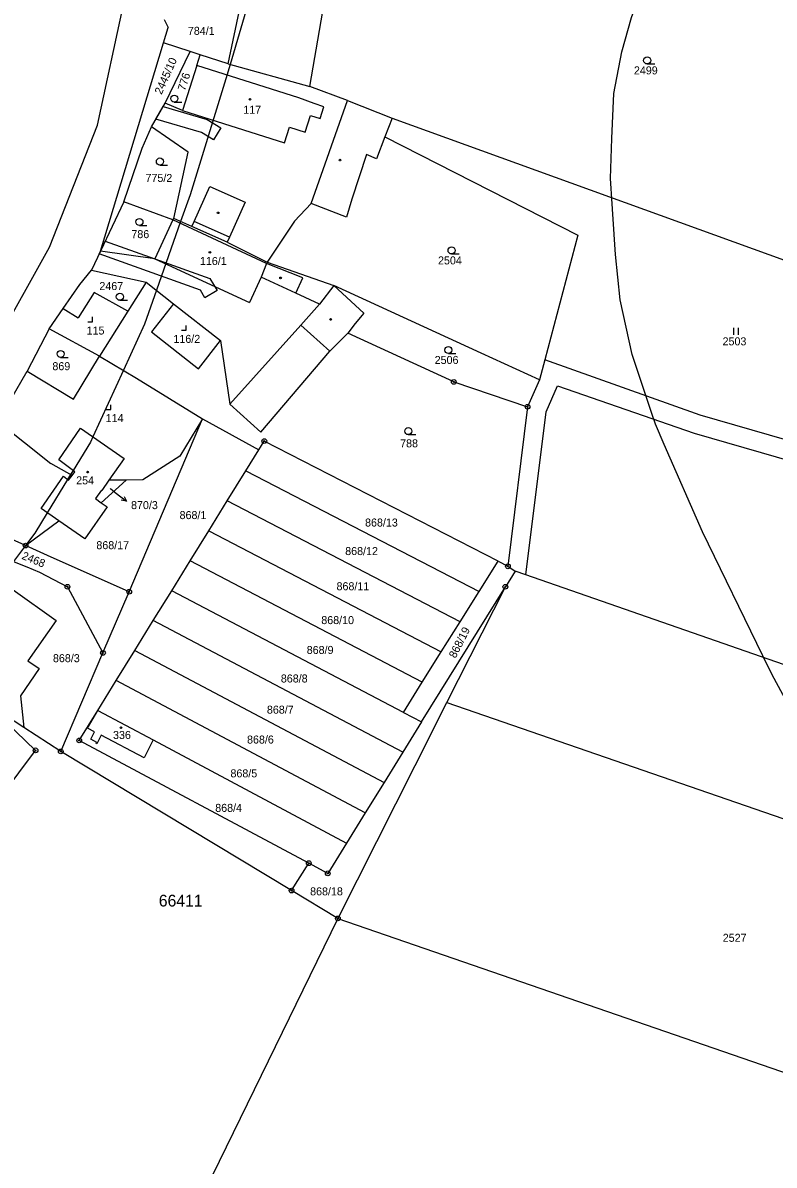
# Model space of a CAD drawing. Extents: x -546762 to -540209, y -1046851 to -1035694.
# Drawn here: x -542624.6 to -542465, y -1040034.9 to -1039792.3 of the extents above; entities that cross this region are included whole.
import ezdxf

# ---------------------------------------------------------------- set-up
doc = ezdxf.new("R2010")
doc.units = 0
for name, color, linetype in [('Vrstva 1', 7, 'Continuous'), ('Vrstva 16', 7, 'Continuous'), ('Vrstva 18', 7, 'Continuous'), ('Vrstva 19', 7, 'Continuous'), ('Vrstva 24', 7, 'Continuous'), ('Vrstva 25', 7, 'Continuous'), ('Vrstva 3', 7, 'Continuous'), ('Vrstva 30', 7, 'Continuous'), ('Vrstva 37', 7, 'Continuous'), ('Vrstva 4', 7, 'Continuous'), ('Vrstva 52', 7, 'Continuous'), ('Vrstva 53', 7, 'Continuous')]:
    doc.layers.add(name, color=color, linetype=linetype)

msp = doc.modelspace()

# ---------------------------------------------------------------- linework, layer by layer
at = {"layer": 'Vrstva 1'}
for p, q in [((-542581, -1039801.03), (-542563.71, -1039805.78)), ((-542581.25, -1039838.88), (-542572.71, -1039843.1)), ((-542559.45, -1039862.04), (-542555.64, -1039858.16)), ((-542523.68, -1039906.64), (-542573.35, -1039881.1)), ((-542577.28, -1039887.46), (-542527.73, -1039913.09)), ((-542531.75, -1039919.5), (-542581.21, -1039893.81)), ((-542585.14, -1039900.17), (-542535.77, -1039925.9)), ((-542539.79, -1039932.31), (-542589.07, -1039906.53)), ((-542527.73, -1039913.09), (-542523.68, -1039906.64)), ((-542523.68, -1039906.64), (-542521.61, -1039907.71)), ((-542543.81, -1039938.73), (-542593.01, -1039912.89)), ((-542531.75, -1039919.5), (-542527.73, -1039913.09)), ((-542535.77, -1039925.9), (-542531.75, -1039919.5)), ((-542539.79, -1039932.31), (-542535.77, -1039925.9)), ((-542543.81, -1039938.73), (-542539.79, -1039932.31)), ((-542625.15, -1039935.18), (-542624.41, -1039941.95)), ((-542610.93, -1039942.11), (-542608.73, -1039938.31)), ((-542608.73, -1039938.31), (-542596.99, -1039944.57)), ((-542543.81, -1039938.73), (-542539.94, -1039940.76)), ((-542609.4, -1039942.89), (-542610.93, -1039942.11)), ((-542610.19, -1039944.45), (-542609.4, -1039942.89)), ((-542608.94, -1039945.09), (-542610.19, -1039944.45)), ((-542608.02, -1039943.6), (-542608.91, -1039945.42)), ((-542598.87, -1039948.36), (-542608.02, -1039943.6)), ((-542596.99, -1039944.57), (-542598.87, -1039948.36)), ((-542596.99, -1039944.57), (-542555.88, -1039966.48)), ((-542563.91, -1039970.75), (-542612.66, -1039944.67)), ((-542609.06, -1039945.33), (-542608.94, -1039945.09)), ((-542608.91, -1039945.42), (-542609.06, -1039945.33)), ((-542567.56, -1039976.57), (-542563.91, -1039970.75)), ((-542559.87, -1039972.91), (-542563.91, -1039970.75))]:
    msp.add_line(p, q, dxfattribs=at)
for points in [[(-542563.71, -1039805.78), (-542556.45, -1039763.93)], [(-542581, -1039801.03), (-542575.76, -1039776.13)], [(-542608.77, -1039813.99), (-542603.21, -1039788.14)], [(-542594.65, -1039791.59), (-542593.79, -1039793.26)], [(-542594.79, -1039796.56), (-542593.79, -1039793.26)], [(-542608.16, -1039840.77), (-542594.79, -1039796.56)], [(-542589.11, -1039798.4), (-542594.79, -1039796.56)], [(-542594.42, -1039809.35), (-542589.11, -1039798.4)], [(-542586.96, -1039799.1), (-542589.11, -1039798.4)], [(-542587.67, -1039801.32), (-542590.72, -1039810.88)], [(-542587.67, -1039801.32), (-542586.96, -1039799.1)], [(-542581, -1039801.03), (-542586.96, -1039799.1)], [(-542555.67, -1039808.79), (-542563.71, -1039805.78)], [(-542555.67, -1039808.79), (-542546.21, -1039812.5)], [(-542597.33, -1039814.38), (-542594.42, -1039809.35)], [(-542590.72, -1039810.88), (-542594.42, -1039809.35)], [(-542546.21, -1039812.5), (-542547.73, -1039816.49)], [(-542546.21, -1039812.5), (-542443.07, -1039849.82)], [(-542619, -1039839.94), (-542608.77, -1039813.99)], [(-542599.3, -1039818.9), (-542597.33, -1039814.38)], [(-542589.53, -1039819.73), (-542597.33, -1039814.38)], [(-542547.73, -1039816.49), (-542549.53, -1039821.2)], [(-542547.73, -1039816.49), (-542506.75, -1039837.36)], [(-542603.17, -1039830.3), (-542599.3, -1039818.9)], [(-542592.6, -1039833.81), (-542589.53, -1039819.73)], [(-542551.62, -1039820.28), (-542554.73, -1039829.75)], [(-542549.53, -1039821.2), (-542551.62, -1039820.28)], [(-542603.17, -1039830.3), (-542608.16, -1039840.77)], [(-542592.75, -1039834.13), (-542603.17, -1039830.3)], [(-542563.38, -1039830.63), (-542566.95, -1039834.4)], [(-542555.92, -1039833.53), (-542563.38, -1039830.63)], [(-542554.73, -1039829.75), (-542555.92, -1039833.53)], [(-542592.75, -1039834.13), (-542596.61, -1039842.42)], [(-542592.75, -1039834.13), (-542592.6, -1039833.81)], [(-542588.72, -1039835.54), (-542592.6, -1039833.81)], [(-542566.95, -1039834.4), (-542572.71, -1039843.1)], [(-542581.25, -1039838.88), (-542588.72, -1039835.54)], [(-542506.75, -1039837.36), (-542513.76, -1039863.86)], [(-542630.3, -1039860.17), (-542619, -1039839.94)], [(-542608.16, -1039840.77), (-542610.07, -1039844.79)], [(-542596.61, -1039842.42), (-542608.16, -1039840.77)], [(-542612.57, -1039847.88), (-542610.07, -1039844.79)], [(-542610.07, -1039844.79), (-542598.45, -1039847.35)], [(-542572.71, -1039843.1), (-542558.58, -1039848.09)], [(-542598.45, -1039847.35), (-542602.33, -1039853.54)], [(-542598.45, -1039847.35), (-542592.62, -1039851.93)], [(-542616.08, -1039852.98), (-542612.57, -1039847.88)], [(-542609.51, -1039849.57), (-542612.9, -1039854.97)], [(-542602.33, -1039853.54), (-542609.51, -1039849.57)], [(-542527.27, -1039862.42), (-542558.58, -1039848.09)], [(-542558.58, -1039848.09), (-542552.22, -1039853.95)], [(-542592.62, -1039851.93), (-542597.31, -1039857.91)], [(-542592.62, -1039851.93), (-542582.67, -1039859.75)], [(-542619.07, -1039857.3), (-542616.08, -1039852.98)], [(-542616.08, -1039852.98), (-542612.9, -1039854.97)], [(-542602.33, -1039853.54), (-542608.33, -1039863.11)], [(-542552.22, -1039853.95), (-542554.03, -1039856.17)], [(-542619.07, -1039857.3), (-542623.71, -1039866.26)], [(-542608.33, -1039863.11), (-542619.07, -1039857.3)], [(-542554.03, -1039856.17), (-542555.64, -1039858.16)], [(-542597.31, -1039857.91), (-542587.33, -1039865.76)], [(-542533.1, -1039868.56), (-542555.64, -1039858.16)], [(-542587.33, -1039865.76), (-542582.67, -1039859.75)], [(-542582.67, -1039859.75), (-542580.71, -1039873.25)], [(-542574.09, -1039879.21), (-542559.45, -1039862.04)], [(-542613.91, -1039872.24), (-542608.33, -1039863.11)], [(-542608.33, -1039863.11), (-542600.49, -1039867.72)], [(-542514.88, -1039868.09), (-542527.27, -1039862.42)], [(-542513.76, -1039863.86), (-542514.88, -1039868.09)], [(-542480.8, -1039875.6), (-542513.76, -1039863.86)], [(-542629.96, -1039876.96), (-542623.71, -1039866.26)], [(-542623.71, -1039866.26), (-542613.91, -1039872.24)], [(-542600.49, -1039867.72), (-542586.46, -1039876.4)], [(-542533.1, -1039868.56), (-542517.43, -1039873.82)], [(-542514.88, -1039868.09), (-542517.43, -1039873.82)], [(-542513.5, -1039874.91), (-542511.05, -1039869.41)], [(-542511.05, -1039869.41), (-542482.01, -1039879.41)], [(-542580.71, -1039873.25), (-542574.09, -1039879.21)], [(-542517.43, -1039873.82), (-542521.61, -1039907.71)], [(-542602.05, -1039913.1), (-542586.46, -1039876.4)], [(-542586.46, -1039876.4), (-542591.3, -1039884.34)], [(-542586.46, -1039876.4), (-542574.5, -1039882.96)], [(-542517.77, -1039909.55), (-542513.5, -1039874.91)], [(-542425.03, -1039891.71), (-542480.8, -1039875.6)], [(-542629.96, -1039876.96), (-542618.71, -1039885.88)], [(-542617.03, -1039885.08), (-542612.4, -1039878.35)], [(-542612.4, -1039878.35), (-542603.11, -1039884.79)], [(-542574.5, -1039882.96), (-542573.35, -1039881.1)], [(-542482.01, -1039879.41), (-542443.54, -1039890.54)], [(-542577.28, -1039887.46), (-542574.5, -1039882.96)], [(-542614.19, -1039888.41), (-542618.71, -1039885.88)], [(-542613.6, -1039887.61), (-542617.03, -1039885.08)], [(-542603.11, -1039884.79), (-542606.36, -1039889.43)], [(-542591.3, -1039884.34), (-542599.17, -1039889.37)], [(-542620.78, -1039895.41), (-542616.04, -1039888.58)], [(-542616.04, -1039888.58), (-542614.92, -1039889.4)], [(-542614.92, -1039889.4), (-542614.19, -1039888.41)], [(-542614.19, -1039888.41), (-542613.6, -1039887.61)], [(-542581.21, -1039893.81), (-542577.28, -1039887.46)], [(-542602.68, -1039889.4), (-542607.98, -1039894.2)], [(-542606.36, -1039889.43), (-542607.87, -1039891.59)], [(-542602.68, -1039889.4), (-542606.36, -1039889.43)], [(-542599.17, -1039889.37), (-542602.68, -1039889.4)], [(-542607.95, -1039891.53), (-542609.21, -1039893.34)], [(-542609.21, -1039893.34), (-542607.98, -1039894.2)], [(-542607.87, -1039891.59), (-542607.95, -1039891.53)], [(-542617.01, -1039898.03), (-542620.78, -1039895.41)], [(-542606.75, -1039895.06), (-542611.51, -1039901.86)], [(-542607.98, -1039894.2), (-542606.75, -1039895.06)], [(-542585.14, -1039900.17), (-542581.21, -1039893.81)], [(-542624.06, -1039903.31), (-542617.01, -1039898.03)], [(-542611.51, -1039901.86), (-542617.01, -1039898.03)], [(-542624.06, -1039903.31), (-542633.71, -1039898.96)], [(-542589.07, -1039906.53), (-542585.14, -1039900.17)], [(-542619.41, -1039905.38), (-542624.06, -1039903.31)], [(-542602.05, -1039913.1), (-542619.41, -1039905.38)], [(-542627.89, -1039906.22), (-542623.78, -1039907.79)], [(-542623.78, -1039907.79), (-542621.09, -1039908.93)], [(-542593.01, -1039912.89), (-542589.07, -1039906.53)], [(-542521.61, -1039907.71), (-542520.07, -1039908.75)], [(-542621.09, -1039908.93), (-542615.16, -1039912.05)], [(-542520.07, -1039908.75), (-542522.15, -1039912.06)], [(-542517.77, -1039909.55), (-542520.07, -1039908.75)], [(-542408.09, -1039947.65), (-542517.77, -1039909.55)], [(-542626.73, -1039912.72), (-542617.54, -1039919.22)], [(-542615.16, -1039912.05), (-542607.62, -1039926.1)], [(-542607.62, -1039926.1), (-542602.05, -1039913.1)], [(-542596.94, -1039919.24), (-542593.01, -1039912.89)], [(-542539.94, -1039940.76), (-542522.15, -1039912.06)], [(-542534.56, -1039936.63), (-542522.15, -1039912.06)], [(-542617.54, -1039919.22), (-542623.6, -1039927.8)], [(-542600.87, -1039925.6), (-542596.94, -1039919.24)], [(-542543.92, -1039947.19), (-542596.94, -1039919.24)], [(-542616.59, -1039947.02), (-542607.62, -1039926.1)], [(-542604.8, -1039931.96), (-542600.87, -1039925.6)], [(-542600.87, -1039925.6), (-542547.91, -1039953.62)], [(-542621.15, -1039929.4), (-542625.15, -1039935.18)], [(-542623.6, -1039927.8), (-542621.15, -1039929.4)], [(-542608.73, -1039938.31), (-542604.8, -1039931.96)], [(-542551.9, -1039960.05), (-542604.8, -1039931.96)], [(-542624.41, -1039941.95), (-542632.54, -1039936.68)], [(-542632.54, -1039936.68), (-542621.94, -1039946.79)], [(-542537.24, -1039941.94), (-542534.56, -1039936.63)], [(-542534.56, -1039936.63), (-542397.78, -1039983.83)], [(-542612.66, -1039944.67), (-542608.73, -1039938.31)], [(-542616.59, -1039947.02), (-542624.41, -1039941.95)], [(-542537.24, -1039941.94), (-542557.72, -1039982.5)], [(-542539.94, -1039940.76), (-542543.92, -1039947.19)], [(-542667.2, -1040007.38), (-542621.94, -1039946.79)], [(-542567.56, -1039976.57), (-542616.59, -1039947.02)], [(-542543.92, -1039947.19), (-542547.91, -1039953.62)], [(-542547.91, -1039953.62), (-542551.9, -1039960.05)], [(-542551.9, -1039960.05), (-542555.88, -1039966.48)], [(-542555.88, -1039966.48), (-542559.87, -1039972.91)], [(-542557.72, -1039982.5), (-542567.56, -1039976.57)], [(-542557.72, -1039982.5), (-542615.49, -1040100.81)], [(-542557.72, -1039982.5), (-542416.72, -1040031.16)]]:
    msp.add_lwpolyline(points, dxfattribs=at)
at = {"layer": 'Vrstva 16'}
msp.add_line((-542605.02, -1039892.01), (-542602.66, -1039893.86), dxfattribs=at)
for points in [[(-542606.03, -1039891.21), (-542605.02, -1039892.01)], [(-542603.14, -1039892.85), (-542602.66, -1039893.86), (-542603.76, -1039893.64)]]:
    msp.add_lwpolyline(points, dxfattribs=at)
at = {"layer": 'Vrstva 24'}
for centre, radius in [((-542533.1, -1039868.56), 0.5), ((-542533.1, -1039868.56), 0.1), ((-542517.43, -1039873.82), 0.5), ((-542517.43, -1039873.82), 0.1), ((-542573.35, -1039881.1), 0.5), ((-542573.35, -1039881.1), 0.1), ((-542624.06, -1039903.31), 0.5), ((-542624.06, -1039903.31), 0.1), ((-542521.61, -1039907.71), 0.5), ((-542521.61, -1039907.71), 0.1), ((-542615.16, -1039912.05), 0.5), ((-542615.16, -1039912.05), 0.1), ((-542602.05, -1039913.1), 0.5), ((-542602.05, -1039913.1), 0.1), ((-542522.15, -1039912.06), 0.5), ((-542522.15, -1039912.06), 0.1), ((-542607.62, -1039926.1), 0.5), ((-542607.62, -1039926.1), 0.1), ((-542612.66, -1039944.67), 0.5), ((-542612.66, -1039944.67), 0.1), ((-542621.94, -1039946.79), 0.5), ((-542621.94, -1039946.79), 0.1), ((-542616.59, -1039947.02), 0.5), ((-542616.59, -1039947.02), 0.1), ((-542563.91, -1039970.75), 0.5), ((-542563.91, -1039970.75), 0.1), ((-542559.87, -1039972.91), 0.5), ((-542559.87, -1039972.91), 0.1), ((-542567.56, -1039976.57), 0.5), ((-542567.56, -1039976.57), 0.1), ((-542557.72, -1039982.5), 0.5), ((-542557.72, -1039982.5), 0.1)]:
    msp.add_circle(centre, radius, dxfattribs=at)
at = {"layer": 'Vrstva 25'}
for p, q in [((-542492.02, -1039801.03), (-542490.42, -1039801.03)), ((-542592.48, -1039809.13), (-542590.88, -1039809.13)), ((-542595.53, -1039822.49), (-542593.93, -1039822.49)), ((-542599.88, -1039835.32), (-542598.28, -1039835.32)), ((-542533.58, -1039841.38), (-542531.98, -1039841.38)), ((-542604.04, -1039851.21), (-542602.44, -1039851.21)), ((-542473.63, -1039858.57), (-542473.63, -1039857.07)), ((-542472.63, -1039858.57), (-542472.63, -1039857.07)), ((-542616.62, -1039863.36), (-542615.02, -1039863.36)), ((-542534.25, -1039862.52), (-542532.65, -1039862.52)), ((-542542.77, -1039879.74), (-542541.17, -1039879.74))]:
    msp.add_line(p, q, dxfattribs=at)
for points in [[(-542610.84, -1039855.76), (-542609.84, -1039855.76), (-542609.84, -1039854.76)], [(-542590.96, -1039857.57), (-542589.96, -1039857.57), (-542589.96, -1039856.57)], [(-542606.94, -1039874.38), (-542605.94, -1039874.38), (-542605.94, -1039873.38)]]:
    msp.add_lwpolyline(points, dxfattribs=at)
for centre, radius in [((-542492.02, -1039800.28), 0.75), ((-542592.48, -1039808.38), 0.75), ((-542576.38, -1039808.52), 0.175), ((-542595.53, -1039821.74), 0.75), ((-542557.29, -1039821.45), 0.175), ((-542583.16, -1039832.64), 0.175), ((-542599.88, -1039834.57), 0.75), ((-542533.58, -1039840.63), 0.75), ((-542584.92, -1039841.02), 0.175), ((-542569.91, -1039846.46), 0.175), ((-542604.04, -1039850.46), 0.75), ((-542559.26, -1039855.29), 0.175), ((-542616.62, -1039862.61), 0.75), ((-542534.25, -1039861.77), 0.75), ((-542542.77, -1039878.99), 0.75), ((-542610.88, -1039887.7), 0.175), ((-542603.8, -1039941.99), 0.175)]:
    msp.add_circle(centre, radius, dxfattribs=at)
at = {"layer": 'Vrstva 3'}
for points in [[(-542587.67, -1039801.32), (-542590.72, -1039810.88)], [(-542566.04, -1039808.22), (-542587.67, -1039801.32)], [(-542562.75, -1039809.41), (-542566.04, -1039808.22)], [(-542590.72, -1039810.88), (-542569.09, -1039817.78)], [(-542560.72, -1039810.11), (-542562.75, -1039809.41)], [(-542561.51, -1039812.59), (-542560.72, -1039810.11)], [(-542564.7, -1039815.51), (-542563.56, -1039811.94)], [(-542563.56, -1039811.94), (-542561.51, -1039812.59)], [(-542569.09, -1039817.78), (-542568.03, -1039814.44)], [(-542568.03, -1039814.44), (-542564.7, -1039815.51)], [(-542592.75, -1039834.13), (-542596.61, -1039842.42)], [(-542572.91, -1039843.4), (-542592.75, -1039834.13)], [(-542596.61, -1039842.42), (-542576.51, -1039851.69)], [(-542572.91, -1039843.4), (-542574.04, -1039846.33)], [(-542574.04, -1039846.33), (-542576.51, -1039851.69)], [(-542617.03, -1039885.08), (-542612.4, -1039878.35)], [(-542612.4, -1039878.35), (-542603.11, -1039884.79)], [(-542613.6, -1039887.61), (-542617.03, -1039885.08)], [(-542603.11, -1039884.79), (-542606.36, -1039889.43)], [(-542620.78, -1039895.41), (-542616.04, -1039888.58)], [(-542616.04, -1039888.58), (-542614.92, -1039889.4)], [(-542614.92, -1039889.4), (-542614.19, -1039888.41)], [(-542614.19, -1039888.41), (-542613.6, -1039887.61)], [(-542606.36, -1039889.43), (-542607.87, -1039891.59)], [(-542607.95, -1039891.53), (-542609.21, -1039893.34)], [(-542609.21, -1039893.34), (-542607.98, -1039894.2)], [(-542607.87, -1039891.59), (-542607.95, -1039891.53)], [(-542617.01, -1039898.03), (-542620.78, -1039895.41)], [(-542606.75, -1039895.06), (-542611.51, -1039901.86)], [(-542607.98, -1039894.2), (-542606.75, -1039895.06)], [(-542611.51, -1039901.86), (-542617.01, -1039898.03)], [(-542626.73, -1039912.72), (-542617.54, -1039919.22)], [(-542617.54, -1039919.22), (-542623.6, -1039927.8)], [(-542621.15, -1039929.4), (-542625.15, -1039935.18)], [(-542623.6, -1039927.8), (-542621.15, -1039929.4)], [(-542610.93, -1039942.11), (-542608.73, -1039938.31)], [(-542608.73, -1039938.31), (-542596.99, -1039944.57)], [(-542609.4, -1039942.89), (-542610.93, -1039942.11)], [(-542610.19, -1039944.45), (-542609.4, -1039942.89)], [(-542608.94, -1039945.09), (-542610.19, -1039944.45)], [(-542608.02, -1039943.6), (-542608.91, -1039945.42)], [(-542598.87, -1039948.36), (-542608.02, -1039943.6)], [(-542596.99, -1039944.57), (-542598.87, -1039948.36)], [(-542609.06, -1039945.33), (-542608.94, -1039945.09)], [(-542608.91, -1039945.42), (-542609.06, -1039945.33)]]:
    msp.add_lwpolyline(points, dxfattribs=at)
at = {"layer": 'Vrstva 30'}
for points in [[(-542585.48, -1039812.8), (-542582.57, -1039814.59), (-542584.14, -1039817.14), (-542586.7, -1039815.56), (-542596.39, -1039812.75), (-542594.84, -1039810.08), (-542585.48, -1039812.8)], [(-542583.4, -1039849.12), (-542585.98, -1039850.66), (-542586.94, -1039849.04), (-542608.43, -1039841.33), (-542608.16, -1039840.77), (-542607.14, -1039838.63), (-542596.61, -1039842.42), (-542584.92, -1039846.58), (-542583.4, -1039849.12)]]:
    msp.add_lwpolyline(points, dxfattribs=at)
at = {"layer": 'Vrstva 37'}
for centre in [(-542576.38, -1039808.52), (-542584.92, -1039841.02), (-542610.88, -1039887.7), (-542603.8, -1039941.99)]:
    msp.add_circle(centre, 0.175, dxfattribs=at)
at = {"layer": 'Vrstva 4'}
for p, q in [((-542563.38, -1039830.63), (-542555.67, -1039808.79)), ((-542572.91, -1039843.4), (-542574.04, -1039846.33)), ((-542565.17, -1039846.46), (-542572.91, -1039843.4)), ((-542558.58, -1039848.09), (-542561.63, -1039852.06))]:
    msp.add_line(p, q, dxfattribs=at)
for points in [[(-542566.04, -1039808.22), (-542587.67, -1039801.32)], [(-542562.75, -1039809.41), (-542566.04, -1039808.22)], [(-542590.72, -1039810.88), (-542569.09, -1039817.78)], [(-542560.72, -1039810.11), (-542562.75, -1039809.41)], [(-542561.51, -1039812.59), (-542560.72, -1039810.11)], [(-542564.7, -1039815.51), (-542563.56, -1039811.94)], [(-542563.56, -1039811.94), (-542561.51, -1039812.59)], [(-542569.09, -1039817.78), (-542568.03, -1039814.44)], [(-542568.03, -1039814.44), (-542564.7, -1039815.51)], [(-542588.25, -1039834.49), (-542584.91, -1039827.02)], [(-542584.91, -1039827.02), (-542577.44, -1039830.35)], [(-542577.44, -1039830.35), (-542580.78, -1039837.82)], [(-542572.91, -1039843.4), (-542592.75, -1039834.13)], [(-542588.72, -1039835.54), (-542588.25, -1039834.49)], [(-542580.78, -1039837.82), (-542588.25, -1039834.49)], [(-542580.78, -1039837.82), (-542581.25, -1039838.88)], [(-542596.61, -1039842.42), (-542576.51, -1039851.69)], [(-542574.04, -1039846.33), (-542576.51, -1039851.69)], [(-542566.68, -1039849.73), (-542574.04, -1039846.33)], [(-542566.68, -1039849.73), (-542565.17, -1039846.46)], [(-542561.63, -1039852.06), (-542566.68, -1039849.73)], [(-542565.62, -1039856.49), (-542561.63, -1039852.06)], [(-542580.71, -1039873.25), (-542565.62, -1039856.49)], [(-542565.62, -1039856.49), (-542559.45, -1039862.04)]]:
    msp.add_lwpolyline(points, dxfattribs=at)
at = {"layer": 'Vrstva 52'}
for points in [[(-542452.16, -1039955.34), (-542465.49, -1039930.76), (-542467.46, -1039926.72), (-542480.26, -1039900.42), (-542488.38, -1039881.87), (-542490.27, -1039877.55), (-542491.11, -1039875.04), (-542495.2, -1039862.76), (-542497.74, -1039851.1), (-542498.78, -1039841.5), (-542499.34, -1039832.92), (-542499.48, -1039830.7), (-542499.83, -1039825.36), (-542499.53, -1039816.84), (-542499.08, -1039807.27), (-542497.44, -1039798.46), (-542495.35, -1039791.13), (-542492.66, -1039783.81), (-542492.07, -1039782.61), (-542489.37, -1039777.09), (-542486.23, -1039771.11), (-542484.12, -1039767.13), (-542482.27, -1039763.63), (-542482.1, -1039763.31)], [(-542573.44, -1039776.75), (-542580.64, -1039801.14), (-542581.55, -1039804.21), (-542589.13, -1039828.79), (-542591.13, -1039834.47), (-542596.27, -1039849.06), (-542598.8, -1039856.26), (-542603.29, -1039866.07), (-542609.76, -1039880.18), (-542610.3, -1039881.36), (-542613.97, -1039887.34), (-542614.52, -1039888.23), (-542615.14, -1039889.24), (-542619.48, -1039896.32), (-542622.13, -1039900.64), (-542624.08, -1039903.29), (-542626.6, -1039906.71)]]:
    msp.add_lwpolyline(points, dxfattribs=at)

# ---------------------------------------------------------------- texts
at = {"layer": 'Vrstva 16'}
msp.add_text('870/3', height=1.7, dxfattribs=at).set_placement((-542601.66, -1039895.56))
at = {"layer": 'Vrstva 18'}
for s, height, p in [('784/1', 1.7, (-542589.59, -1039794.84)), ('2499', 1.7, (-542494.84, -1039803.24)), ('775/2', 1.7, (-542598.59, -1039826.08)), ('786', 1.7, (-542601.59, -1039838.02)), ('2504', 1.7, (-542536.45, -1039843.59)), ('2467', 1.7, (-542608.39, -1039849.04)), ('2503', 1.7, (-542476.01, -1039860.78)), ('869', 1.7, (-542618.37, -1039866.06)), ('2506', 1.7, (-542537.16, -1039864.73)), ('788', 1.7, (-542544.5, -1039882.44)), ('870/3', 0.1, (-542606.22, -1039891.21)), ('868/1', 1.7, (-542591.35, -1039897.68)), ('868/13', 1.7, (-542551.95, -1039899.26)), ('868/17', 1.7, (-542609.03, -1039904.07)), ('868/12', 1.7, (-542556.17, -1039905.32)), ('868/11', 1.7, (-542558.01, -1039912.79)), ('868/10', 1.7, (-542561.25, -1039919.98)), ('868/9', 1.7, (-542564.34, -1039926.32)), ('868/3', 1.7, (-542618.25, -1039928.07)), ('868/8', 1.7, (-542569.84, -1039932.38)), ('868/7', 1.7, (-542572.8, -1039939)), ('868/6', 1.7, (-542577.02, -1039945.35)), ('868/5', 1.7, (-542580.54, -1039952.53)), ('868/4', 1.7, (-542583.78, -1039959.86)), ('868/18', 1.7, (-542563.62, -1039977.59)), ('2527', 1.7, (-542475.97, -1039987.45))]:
    msp.add_text(s, height=height, dxfattribs=at).set_placement(p)
for s, rotation, p in [('2445/10', 66.0074, (-542595.19, -1039807.65)), ('776', 72.7781, (-542590.17, -1039806.84)), ('2468', 337.6527, (-542625.01, -1039906.09)), ('868/19', 63, (-542532.74, -1039927.36))]:
    msp.add_text(s, height=1.7, rotation=rotation, dxfattribs=at).set_placement(p)
at = {"layer": 'Vrstva 19'}
for s, p in [('117', (-542577.82, -1039811.59)), ('116/1', (-542587.03, -1039843.72)), ('115', (-542611.1, -1039858.48)), ('116/2', (-542592.66, -1039860.26)), ('114', (-542607.05, -1039877.08)), ('254', (-542613.32, -1039890.3)), ('336', (-542605.49, -1039944.38))]:
    msp.add_text(s, height=1.7, dxfattribs=at).set_placement(p)
at = {"layer": 'Vrstva 53'}
msp.add_text('66411', height=2.5, dxfattribs=at).set_placement((-542595.76, -1039979.96))

doc.saveas('drawing.dxf')
